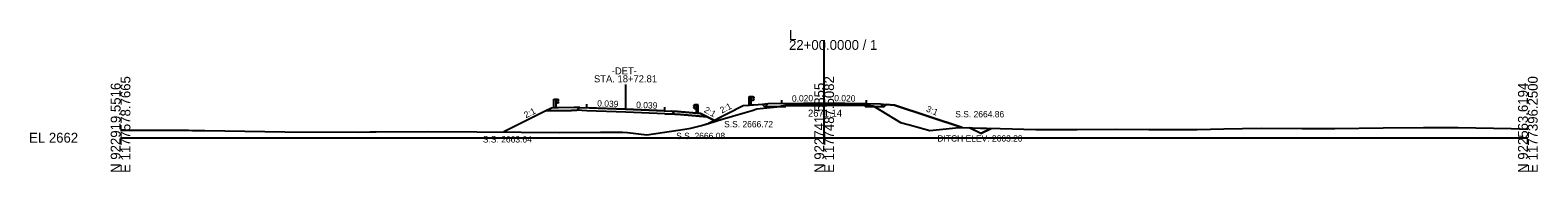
# Model space of a CAD drawing. Extents: x -26 to 1403, y -10 to 9563.
# Drawn here: x 974.3 to 1402.8, y 1990.3 to 2030.5 of the extents above; entities that cross this region are included whole.
import ezdxf

# ---------------------------------------------------------------- set-up
doc = ezdxf.new("R2010")
doc.units = 0
for name, color, linetype in [('Exist Cross Section Cell', 7, 'Continuous'), ('Exist XS Center Line Elevation Label', 7, 'Continuous'), ('Exist XS Ground Line', 7, 'Continuous'), ('Prop XS DDE Earthwork Shape', 7, 'Continuous'), ('Prop XS Ditch Slope Text', 7, 'Continuous'), ('Prop XS Ditch Standard Text', 7, 'Continuous'), ('Prop XS Dump Level', 7, 'Continuous'), ('Prop XS Earthwork Shape', 7, 'Continuous'), ('Prop XS EOT Tick Mark', 7, 'Continuous'), ('Prop XS Finish Grade', 7, 'Continuous'), ('Prop XS Finish Grade Earthwork', 7, 'Continuous'), ('Prop XS Finish Grade Paved Shoulder', 7, 'Continuous'), ('Prop XS Finish Grade Pavement', 7, 'Continuous'), ('Prop XS Guardrail', 7, 'Continuous'), ('Prop XS Pvmt Edge Slope', 7, 'Continuous'), ('Prop XS SE Text', 7, 'Continuous'), ('Prop XS Shoulder Borrow Shape', 7, 'Continuous'), ('Prop XS Side Slope Text', 7, 'Continuous'), ('Prop XS SS Elevation Text', 7, 'Continuous'), ('Prop XS Subgrade Earthwork', 7, 'Continuous'), ('Prop XS Vertical Lines', 7, 'Continuous'), ('Prop XS Wedging', 7, 'Continuous')]:
    doc.layers.add(name, color=color, linetype=linetype)

msp = doc.modelspace()

# ---------------------------------------------------------------- linework, layer by layer
at = {"layer": 'Exist Cross Section Cell'}
for p, q in [((1200, 2000), (1200, 2027.75)), ((1000, 2000), (1200, 2000)), ((1200, 2000), (1400, 2000))]:
    msp.add_line(p, q, dxfattribs=at)
at = {"layer": 'Exist XS Ground Line'}
for p, q in [((1171, 2005.26), (1177.54, 2007.18)), ((1177.54, 2007.18), (1179.55, 2007.73)), ((1179.55, 2007.73), (1180.82, 2008.16)), ((1180.82, 2008.16), (1187.4, 2008.91)), ((1187.4, 2008.91), (1188.35, 2009.02)), ((1188.35, 2009.02), (1188.7, 2009.06)), ((1188.7, 2009.06), (1189.05, 2009.06)), ((1189.05, 2009.06), (1200.14, 2009.14)), ((1200.14, 2009.14), (1200.77, 2009.15)), ((1200.77, 2009.15), (1211.61, 2009.25)), ((1211.61, 2009.25), (1213.88, 2008.95)), ((1213.88, 2008.95), (1214.23, 2008.89)), ((1214.23, 2008.89), (1216.08, 2007.76)), ((1216.08, 2007.76), (1221.68, 2004.33)), ((1000, 2002.1), (1016.76, 2002.1)), ((1016.76, 2002.1), (1019.28, 2002.1)), ((1019.28, 2002.1), (1020.42, 2002.09)), ((1020.42, 2002.09), (1023.97, 2002.04)), ((1023.97, 2002.04), (1046.67, 2001.7)), ((1046.67, 2001.7), (1067.66, 2001.62)), ((1067.66, 2001.62), (1070.86, 2001.64)), ((1070.86, 2001.64), (1072.61, 2001.64)), ((1072.61, 2001.64), (1087.63, 2001.78)), ((1087.63, 2001.78), (1101.27, 2001.69)), ((1101.27, 2001.69), (1113.87, 2001.61)), ((1113.87, 2001.61), (1124.85, 2001.5)), ((1124.85, 2001.5), (1136.4, 2001.56)), ((1136.4, 2001.56), (1142.64, 2001.61)), ((1142.64, 2001.61), (1144.13, 2001.44)), ((1144.13, 2001.44), (1149.62, 2000.81)), ((1149.62, 2000.81), (1160.34, 2002.45)), ((1160.34, 2002.45), (1162.13, 2002.69)), ((1162.13, 2002.69), (1165.16, 2003.5)), ((1165.16, 2003.5), (1171, 2005.26)), ((1221.68, 2004.33), (1224.23, 2003.62)), ((1224.23, 2003.62), (1230, 2002.05)), ((1230, 2002.05), (1236.49, 2002.71)), ((1236.49, 2002.71), (1238.3, 2002.88)), ((1238.3, 2002.88), (1250.05, 2002.6)), ((1250.05, 2002.6), (1260.16, 2002.33)), ((1260.16, 2002.33), (1271.9, 2002.35)), ((1271.9, 2002.35), (1282.72, 2002.41)), ((1282.72, 2002.41), (1292.27, 2002.36)), ((1292.27, 2002.36), (1305.99, 2002.32)), ((1305.99, 2002.32), (1313.63, 2002.48)), ((1313.63, 2002.48), (1324.19, 2002.7)), ((1324.19, 2002.7), (1335.85, 2002.6)), ((1335.85, 2002.6), (1345.17, 2002.63)), ((1345.17, 2002.63), (1358.89, 2002.77)), ((1358.89, 2002.77), (1370.35, 2002.93)), ((1370.35, 2002.93), (1380.15, 2002.89)), ((1380.15, 2002.89), (1395.26, 2002.57)), ((1395.26, 2002.57), (1400, 2002.47))]:
    msp.add_line(p, q, dxfattribs=at)
at = {"layer": 'Prop XS DDE Earthwork Shape'}
msp.add_lwpolyline([(1241.27, 2002.81), (1247.42, 2002.66), (1244.49, 2001.2)], close=True, dxfattribs=at)
at = {"layer": 'Prop XS Dump Level'}
for p, q in [((1188, 2009.68), (1200, 2009.92)), ((1200, 2009.92), (1212, 2009.68)), ((1130.51, 2008.59), (1143.58, 2008.07)), ((1143.58, 2008.07), (1132.51, 2008.51)), ((1154.66, 2007.64), (1143.58, 2008.07)), ((1143.58, 2008.07), (1156.66, 2007.56))]:
    msp.add_line(p, q, dxfattribs=at)
at = {"layer": 'Prop XS Earthwork Shape'}
for p, q in [((1120.87, 2007.61), (1108.94, 2001.64)), ((1128.14, 2007.76), (1120.87, 2007.61)), ((1129.71, 2007.79), (1128.14, 2007.76)), ((1132.51, 2007.68), (1129.71, 2007.79)), ((1143.58, 2007.24), (1132.51, 2007.68)), ((1154.66, 2006.8), (1143.58, 2007.24)), ((1157.53, 2006.69), (1154.66, 2006.8)), ((1159.14, 2006.56), (1157.53, 2006.69)), ((1166.72, 2005.96), (1159.14, 2006.56)), ((1168.78, 2004.93), (1166.72, 2005.96)), ((1177, 2009.04), (1168.78, 2004.93)), ((1171, 2005.26), (1177.54, 2007.18)), ((1177.54, 2007.18), (1179.55, 2007.73)), ((1179.55, 2007.73), (1180.82, 2008.16)), ((1182.43, 2009.47), (1180, 2009.28)), ((1180.82, 2008.16), (1186.55, 2008.81)), ((1183.15, 2008.75), (1182.43, 2009.47)), ((1186.55, 2008.81), (1183.15, 2008.75)), ((1187.4, 2008.91), (1186.55, 2008.81)), ((1186.55, 2008.81), (1189.05, 2008.86)), ((1188.35, 2009.02), (1187.4, 2008.91)), ((1188.7, 2009.06), (1188.35, 2009.02)), ((1189.05, 2009.06), (1188.7, 2009.06)), ((1189.05, 2008.86), (1189.05, 2009.06)), ((1213.88, 2008.95), (1211.61, 2009.25)), ((1211.61, 2009.25), (1211.61, 2008.85)), ((1211.61, 2008.85), (1214.39, 2008.8)), ((1214.23, 2008.89), (1213.88, 2008.95)), ((1214.39, 2008.8), (1214.23, 2008.89)), ((1216.85, 2008.75), (1214.39, 2008.8)), ((1214.39, 2008.8), (1216.08, 2007.76)), ((1216.08, 2007.76), (1221.68, 2004.33)), ((1217.57, 2009.47), (1216.85, 2008.75)), ((1220, 2009.28), (1217.57, 2009.47)), ((1239.25, 2002.86), (1220, 2009.28)), ((1108.94, 2001.64), (1113.87, 2001.61)), ((1113.87, 2001.61), (1124.85, 2001.5)), ((1124.85, 2001.5), (1136.4, 2001.56)), ((1136.4, 2001.56), (1142.64, 2001.61)), ((1142.64, 2001.61), (1144.13, 2001.44)), ((1144.13, 2001.44), (1149.62, 2000.81)), ((1149.62, 2000.81), (1160.34, 2002.45)), ((1160.34, 2002.45), (1162.13, 2002.69)), ((1162.13, 2002.69), (1165.16, 2003.5)), ((1165.16, 2003.5), (1167.09, 2004.08)), ((1167.09, 2004.08), (1168.78, 2004.93)), ((1168.78, 2004.93), (1167.09, 2004.08)), ((1168.78, 2004.93), (1167.09, 2004.08)), ((1167.09, 2004.08), (1169.19, 2004.72)), ((1167.09, 2004.08), (1169.19, 2004.72)), ((1169.19, 2004.72), (1168.78, 2004.93)), ((1169.19, 2004.72), (1168.78, 2004.93)), ((1168.78, 2004.93), (1169.19, 2004.72)), ((1169.19, 2004.72), (1171, 2005.26)), ((1221.68, 2004.33), (1224.23, 2003.62)), ((1224.23, 2003.62), (1230, 2002.05)), ((1230, 2002.05), (1236.49, 2002.71)), ((1236.49, 2002.71), (1238.3, 2002.88)), ((1238.3, 2002.88), (1239.25, 2002.86))]:
    msp.add_line(p, q, dxfattribs=at)
msp.add_lwpolyline([(1180, 2009.28), (1179.18, 2009.21), (1178.68, 2009.17), (1177, 2009.04)], dxfattribs=at)
at = {"layer": 'Prop XS EOT Tick Mark'}
for p, q in [((1188, 2009.68), (1188, 2010.68)), ((1212, 2009.68), (1212, 2010.68)), ((1132.51, 2008.51), (1132.51, 2009.51)), ((1154.66, 2007.64), (1154.66, 2008.64))]:
    msp.add_line(p, q, dxfattribs=at)
at = {"layer": 'Prop XS Finish Grade'}
for p, q in [((1130.51, 2008.59), (1128.94, 2008.56)), ((1156.66, 2007.56), (1158.27, 2007.43)), ((1184, 2009.6), (1182.43, 2009.47)), ((1216, 2009.6), (1217.57, 2009.47))]:
    msp.add_line(p, q, dxfattribs=at)
at = {"layer": 'Prop XS Finish Grade Earthwork'}
for p, q in [((1120.87, 2007.61), (1108.94, 2001.64)), ((1122.51, 2008.43), (1120.87, 2007.61)), ((1124.51, 2008.47), (1122.51, 2008.43)), ((1128.94, 2008.56), (1124.51, 2008.47)), ((1158.27, 2007.43), (1162.67, 2007.08)), ((1162.67, 2007.08), (1164.82, 2006.91)), ((1164.82, 2006.91), (1166.72, 2005.96)), ((1166.72, 2005.96), (1169.19, 2004.72)), ((1177, 2009.04), (1167.09, 2004.08)), ((1180, 2009.28), (1177, 2009.04)), ((1182.43, 2009.47), (1180, 2009.28)), ((1217.57, 2009.47), (1220, 2009.28)), ((1220, 2009.28), (1239.25, 2002.86)), ((1239.25, 2002.86), (1241.25, 2002.82)), ((1244.49, 2001.2), (1241.25, 2002.82)), ((1244.49, 2001.2), (1247.42, 2002.66))]:
    msp.add_line(p, q, dxfattribs=at)
at = {"layer": 'Prop XS Finish Grade Paved Shoulder'}
for p, q in [((1188, 2009.68), (1184, 2009.6)), ((1212, 2009.68), (1216, 2009.6))]:
    msp.add_line(p, q, dxfattribs=at)
at = {"layer": 'Prop XS Finish Grade Pavement'}
for p, q in [((1188, 2009.68), (1200, 2009.92)), ((1200, 2009.92), (1212, 2009.68)), ((1130.51, 2008.59), (1143.58, 2008.07)), ((1143.58, 2008.07), (1156.66, 2007.56))]:
    msp.add_line(p, q, dxfattribs=at)
at = {"layer": 'Prop XS Guardrail'}
for p, q in [((1123.19, 2010.94), (1123.69, 2010.94)), ((1123.19, 2008.44), (1123.19, 2010.94)), ((1123.69, 2010.94), (1124.19, 2010.94)), ((1123.69, 2010.94), (1123.69, 2008.44)), ((1124.19, 2010.94), (1124.48, 2010.74)), ((1124.48, 2010.62), (1124.19, 2010.42)), ((1124.19, 2010.42), (1124.19, 2010.33)), ((1124.19, 2010.33), (1124.48, 2010.13)), ((1124.48, 2010.01), (1124.19, 2009.81)), ((1124.48, 2010.74), (1124.51, 2010.68)), ((1124.51, 2010.68), (1124.48, 2010.62)), ((1124.48, 2010.13), (1124.51, 2010.07)), ((1124.51, 2010.07), (1124.48, 2010.01)), ((1178.68, 2011.67), (1179.18, 2011.67)), ((1178.68, 2009.17), (1178.68, 2011.67)), ((1179.18, 2011.67), (1179.68, 2011.67)), ((1179.18, 2011.67), (1179.18, 2009.17)), ((1179.68, 2010.54), (1179.18, 2010.54)), ((1179.68, 2011.67), (1179.97, 2011.47)), ((1179.97, 2011.35), (1179.68, 2011.15)), ((1179.68, 2011.15), (1179.68, 2011.06)), ((1179.68, 2011.06), (1179.97, 2010.86)), ((1179.97, 2010.74), (1179.68, 2010.54)), ((1179.97, 2011.47), (1180, 2011.41)), ((1180, 2011.41), (1179.97, 2011.35)), ((1179.97, 2010.86), (1180, 2010.8)), ((1180, 2010.8), (1179.97, 2010.74)), ((1124.19, 2009.81), (1123.69, 2009.81)), ((1162.84, 2009.18), (1162.81, 2009.12)), ((1162.81, 2009.12), (1162.84, 2009.06)), ((1162.84, 2008.57), (1162.81, 2008.51)), ((1162.81, 2008.51), (1162.84, 2008.45)), ((1163.13, 2009.38), (1162.84, 2009.18)), ((1162.84, 2009.06), (1163.13, 2008.86)), ((1163.13, 2008.77), (1162.84, 2008.57)), ((1162.84, 2008.45), (1163.13, 2008.25)), ((1163.63, 2009.38), (1163.13, 2009.38)), ((1163.13, 2008.86), (1163.13, 2008.77)), ((1163.13, 2008.25), (1163.63, 2008.25)), ((1164.13, 2009.38), (1163.63, 2009.38)), ((1163.63, 2009.38), (1163.63, 2006.88)), ((1164.13, 2006.88), (1164.13, 2009.38))]:
    msp.add_line(p, q, dxfattribs=at)
at = {"layer": 'Prop XS Pvmt Edge Slope'}
for p, q in [((1130.51, 2008.59), (1129.71, 2007.79)), ((1156.66, 2007.56), (1157.53, 2006.69)), ((1184, 2009.6), (1183.15, 2008.75)), ((1216, 2009.6), (1216.85, 2008.75))]:
    msp.add_line(p, q, dxfattribs=at)
at = {"layer": 'Prop XS Shoulder Borrow Shape'}
for p, q in [((1122.51, 2008.43), (1120.87, 2007.61)), ((1120.87, 2007.61), (1128.14, 2007.76)), ((1128.94, 2008.56), (1124.51, 2008.47)), ((1128.14, 2007.76), (1129.71, 2007.79)), ((1130.51, 2008.59), (1128.94, 2008.56)), ((1129.71, 2007.79), (1130.51, 2008.59)), ((1158.27, 2007.43), (1156.66, 2007.56)), ((1156.66, 2007.56), (1157.53, 2006.69)), ((1157.53, 2006.69), (1159.14, 2006.56)), ((1162.67, 2007.08), (1158.27, 2007.43)), ((1159.14, 2006.56), (1166.72, 2005.96)), ((1163.63, 2007), (1162.67, 2007.08)), ((1166.72, 2005.96), (1164.82, 2006.91))]:
    msp.add_line(p, q, dxfattribs=at)
for points in [[(1124.51, 2008.47), (1123.69, 2008.45), (1123.19, 2008.44), (1122.51, 2008.43)], [(1164.82, 2006.91), (1164.13, 2006.96), (1163.63, 2007)]]:
    msp.add_lwpolyline(points, dxfattribs=at)
at = {"layer": 'Prop XS Subgrade Earthwork'}
for p, q in [((1128.14, 2007.76), (1120.87, 2007.61)), ((1129.71, 2007.79), (1128.14, 2007.76)), ((1132.51, 2007.68), (1129.71, 2007.79)), ((1143.58, 2007.24), (1132.51, 2007.68)), ((1154.66, 2006.8), (1143.58, 2007.24)), ((1154.66, 2006.8), (1157.53, 2006.69)), ((1157.53, 2006.69), (1159.14, 2006.56)), ((1159.14, 2006.56), (1166.72, 2005.96)), ((1183.15, 2008.75), (1182.43, 2009.47)), ((1189.05, 2008.86), (1183.15, 2008.75)), ((1189.05, 2008.86), (1189.05, 2009.07)), ((1211.61, 2008.85), (1211.61, 2009.25)), ((1211.61, 2008.85), (1216.85, 2008.75)), ((1216.85, 2008.75), (1217.57, 2009.47))]:
    msp.add_line(p, q, dxfattribs=at)
at = {"layer": 'Prop XS Vertical Lines'}
msp.add_line((1143.58, 2008.07), (1143.58, 2015.07), dxfattribs=at)
at = {"layer": 'Prop XS Wedging'}
for points in [[(1189.05, 2009.07), (1189.05, 2009.45), (1200, 2009.67), (1200.14, 2009.66), (1200.77, 2009.65), (1211.61, 2009.43), (1211.61, 2009.25), (1200.77, 2009.15), (1200.14, 2009.14), (1200, 2009.14)], [(1189.05, 2009.07), (1189.05, 2009.45), (1200, 2009.67), (1200.14, 2009.66), (1200.77, 2009.65), (1211.61, 2009.43), (1211.61, 2009.25), (1211.61, 2009.25), (1200.77, 2009.15), (1200.14, 2009.14), (1200, 2009.14)], [(1197.77, 2009.13), (1198.02, 2009.38), (1200, 2009.42), (1200.14, 2009.41), (1200.73, 2009.4), (1200.98, 2009.16), (1200.14, 2009.14), (1200, 2009.14)]]:
    msp.add_lwpolyline(points, close=True, dxfattribs=at)

# ---------------------------------------------------------------- texts
at = {"layer": 'Exist Cross Section Cell'}
for s, p in [('22+00.0000 / 1', (1190, 2024.95)), ('L', (1190, 2027.75)), ('EL 2662', (974, 1998.6))]:
    msp.add_text(s, height=2.8, dxfattribs=at).set_placement(p)
for s, p in [('N 922919.5516', (1000, 1990)), ('E 1177578.7665', (1002.8, 1990)), ('N 922741.5855', (1200, 1990)), ('E 1177487.5082', (1202.8, 1990)), ('N 922563.6194', (1400, 1990)), ('E 1177396.2500', (1402.8, 1990))]:
    msp.add_text(s, height=2.8, rotation=90, dxfattribs=at).set_placement(p)
at = {"layer": 'Exist XS Center Line Elevation Label'}
msp.add_text('2671.14', height=2, dxfattribs=at).set_placement((1195.41, 2005.99))
at = {"layer": 'Prop XS Ditch Slope Text'}
msp.add_text('2:1', height=1.8, rotation=330.9374, dxfattribs=at).set_placement((1165.67, 2007.37))
at = {"layer": 'Prop XS Ditch Standard Text'}
msp.add_text('DITCH ELEV. 2663.20', height=1.8, dxfattribs=at).set_placement((1232.16, 1998.9))
at = {"layer": 'Prop XS Dump Level'}
for s, p in [('Case1', (1124.51, 2008.31)), ('Case1', (1162.66, 2006.96)), ('Case2', (1180, 2009.24)), ('Case2', (1220, 2009.24))]:
    msp.add_text(s, height=0.04, dxfattribs=at).set_placement(p)
at = {"layer": 'Prop XS SE Text'}
for s, rotation, p in [('0.039', 357.7391, (1135.45, 2008.89)), ('0.039', 357.741, (1146.53, 2008.46)), ('0.020', 1.1458, (1190.84, 2010.23)), ('0.020', 358.8542, (1202.84, 2010.36))]:
    msp.add_text(s, height=1.8, rotation=rotation, dxfattribs=at).set_placement(p)
at = {"layer": 'Prop XS Side Slope Text'}
for s, rotation, p in [('2:1', 26.5651, (1115.21, 2005.49)), ('2:1', 26.5651, (1170.89, 2006.86)), ('3:1', 337.382, (1228.82, 2007.51))]:
    msp.add_text(s, height=1.8, rotation=rotation, dxfattribs=at).set_placement(p)
at = {"layer": 'Prop XS SS Elevation Text'}
for s, p in [('S.S. 2664.86', (1237.24, 2005.78)), ('S.S. 2666.08', (1157.92, 1999.6)), ('S.S. 2666.72', (1171.55, 2002.95)), ('S.S. 2663.64', (1102.97, 1998.64))]:
    msp.add_text(s, height=1.8, dxfattribs=at).set_placement(p)
at = {"layer": 'Prop XS Vertical Lines'}
for s, p in [('-DET-', (1139.62, 2017.98)), ('STA. 18+72.81', (1134.57, 2015.73))]:
    msp.add_text(s, height=2, dxfattribs=at).set_placement(p)

doc.saveas('drawing.dxf')
